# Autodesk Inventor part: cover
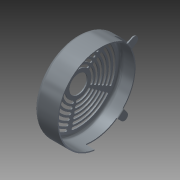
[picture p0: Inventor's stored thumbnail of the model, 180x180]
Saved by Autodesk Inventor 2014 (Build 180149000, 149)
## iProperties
Created: 2002-07
Part Number: cover
Document SubType Name: Modeling
Designer: ales
Density: 1 g/cm^3
Material: Generic
Appearance: Zinc
Control State: 0
Master: False
Checked Out: False
Shininess: 64.0
Length Units: 11269
Angle Units: 11279
Time Units: 11290
Mass Units: 11283
Length Display Precision: 3
Angle Display Precision: 2
Density: 0.0
Volumn: 0.0
Area: 0.0
PropertySet Name: Model Information
Author: PaulN
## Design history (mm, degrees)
sketch "Sketch1"
  geometry: L1 (-8.825, 0)-(-8.825, 107); L2 (3.175, 119)-(31.175, 119); L3 (-5.825, 0)-(-5.825, 107); L4 (3.175, 116)-(31.175, 116); L5 (-8.825, 0)-(-5.825, 0); L6 (31.175, 116)-(31.175, 119); L7 (-19.807, 0)-(39.672, 0) reference; A1 r 12 centre (3.175, 107) between (3.175, 119) and (-8.825, 107); A2 r 9 centre (3.175, 107) between (3.175, 116) and (-5.825, 107)
  constraints: 12 end point, 4 point on circle, 3 perpendicular, 2 centre point, 2 tangent, 1 collinear, 1 parallel, 1 vertical, 2 other
  dimensions: "d0" = 12 radius of A1; "d1" = 3 distance between parallel lines of L2 L4; "d3" = 40 distance between parallel lines of L1 L6; "d21" = 232 diameter of L4 L7
revolve "Revolution1" sketch "Sketch1" stored, may be unused: angle "d4" = 90 deg
sketch "Sketch2"
  geometry: L1 (-166.6, 0)-(166.6, 0) reference; L2 (32.997, 62.87)-(36.25, 69.068); L3 (38.092, 73.743)-(41.305, 79.962); L4 (43.183, 84.618)-(46.365, 90.853); L5 (62.412, 3.5)-(74.421, 3.5); L6 (74.421, 3.5)-(86.429, 3.5); L7 (86.429, 3.5)-(98.438, 3.5); L8 (0, 0)-(8.438, 18.096); L9 (27.894, 52.001)-(31.203, 58.169); L10 (22.778, 41.14)-(26.169, 47.264); L11 (50.403, 3.5)-(62.412, 3.5); L12 (17.637, 30.293)-(21.159, 36.343); L13 (38.395, 3.5)-(50.403, 3.5); C1 r 107 at (0, 0) reference; A1 r 102 centre (0, 0) between (101.936, 3.624) and (46.365, 90.853); A2 r 95 centre (0, 0) between (94.94, 3.376) and (43.183, 84.618); A3 r 3.5 centre (44.774, 87.736) between (46.365, 90.853) and (43.183, 84.618); A4 r 3.5 centre (98.438, 3.5) between (94.94, 3.376) and (101.936, 3.624); A5 r 90 centre (0, 0) between (89.926, 3.642) and (41.305, 79.962); A6 r 83 centre (0, 0) between (82.932, 3.358) and (38.092, 73.743); A7 r 3.5 centre (39.699, 76.852) between (41.305, 79.962) and (38.092, 73.743); A8 r 3.5 centre (86.429, 3.5) between (82.932, 3.358) and (89.926, 3.642); A9 r 78.003 centre (0, 0) between (77.917, 3.664) and (36.25, 69.068); A10 r 71.003 centre (0, 0) between (70.924, 3.336) and (32.997, 62.87); A11 r 3.5 centre (34.624, 65.969) between (36.25, 69.068) and (32.997, 62.87); A12 r 3.5 centre (74.421, 3.5) between (70.924, 3.336) and (77.917, 3.664); A13 r 66.01 centre (0, 0) between (65.906, 3.696) and (31.203, 58.169); A14 r 59.01 centre (0, 0) between (58.917, 3.304) and (27.894, 52.001); A15 r 3.5 centre (29.548, 55.085) between (31.203, 58.169) and (27.894, 52.001); A16 r 3.5 centre (62.412, 3.5) between (58.917, 3.304) and (65.906, 3.696); A17 r 54.025 centre (0, 0) between (53.895, 3.742) and (26.169, 47.264); A18 r 47.025 centre (0, 0) between (46.912, 3.258) and (22.778, 41.14); A19 r 3.5 centre (24.473, 44.202) between (26.169, 47.264) and (22.778, 41.14); A20 r 3.5 centre (50.403, 3.5) between (46.912, 3.258) and (53.895, 3.742); A21 r 42.054 centre (0, 0) between (41.88, 3.818) and (21.159, 36.343); A22 r 35.054 centre (0, 0) between (34.909, 3.182) and (17.637, 30.293); A23 r 3.5 centre (19.398, 33.318) between (21.159, 36.343) and (17.637, 30.293); A24 r 3.5 centre (38.395, 3.5) between (34.909, 3.182) and (41.88, 3.818)
  constraints: 49 point on circle, 33 tangent, 24 centre point, 24 end point, 12 coincident, 9 equal length, 3 collinear
  dimensions: "d6" = 5 radial gap between concentric circles of A1 C1; "d7" = 7 radial gap between concentric circles of A1 A2; "d16" = 5 radial gap between concentric circles of A5 A2 (= d6); "d17" = 65 deg angle of L1 L8
extrude "Extrusion1" cut sketch "Sketch2" stored distance "d10" = 25.4; taper "d11" = 0 deg
pattern_circular "Circular Pattern1" dims angle "d14" = 360 deg
sketch "Sketch3"
  geometry: C1 r 25 at (0, 0); 1 further point
  constraints: 1 centre point, 1 coincident
  dimensions: "d18" = 50 diameter of C1
extrude "Extrusion2" cut sketch "Sketch3" stored distance "d19" = 25.4; taper "d20" = 0 deg
sketch "Sketch4"
  geometry: L1 (58, 100.459)-(59.5, 103.057); L2 (0, 0)-(0, 19.788); L3 (-18.174, -114.567)-(-18.436, -117.563); A1 r 116 centre (0, 0) between (58, 100.459) and (-18.174, -114.567) reference; A2 r 119 centre (0, 0) between (59.5, 103.057) and (-18.436, -117.563) reference
  constraints: 6 end point, 4 point on circle, 1 point on line, 1 vertical
  dimensions: "d22" = 30 deg angle of L1 L2; "d23" = 5 deg angle of L3 L2
extrude "Extrusion3" join sketch "Sketch4" distance "d24" = 25; taper "d25" = 0 deg
fillet "Fillet1" dims "d26" = 3
sketch "Sketch5"
  geometry: L1 (77.134, 107.423)-(67.627, 97.916); L2 (92.397, 94.616)-(84.685, 83.603); L3 (0, 0)-(147.005, 0); L4 (0, 0)-(84.205, 100.352); L5 (84.685, 83.603)-(82.748, 81.294); L6 (67.627, 97.916)-(65.69, 95.608); A1 r 119 centre (0, 0) between (24.72, -116.404) and (24.72, 116.404) reference; A2 r 116 centre (0, 0) between (23.97, -113.496) and (24.171, 113.454) reference; A3 r 10 centre (84.205, 100.352) between (92.397, 94.616) and (77.134, 107.423); 1 further point
  constraints: 12 end point, 9 point on circle, 3 point on line, 2 parallel, 2 tangent, 1 centre point, 1 horizontal
  dimensions: "d27" = 20 diameter of A3; "d28" = 50 deg angle of L3 L4; "d29" = 12 distance of L4.end point (76.492, 91.159); "d31" = 5 deg angle of L1 L4; "d32" = 5 deg angle of L4 L2
extrude "Extrusion4" join sketch "Sketch5" distance "d33" = 3; taper "d34" = 0 deg
fillet "Fillet2" dims "d35" = 3
pattern_circular "Circular Pattern2" dims angle "d38" = 80 deg
body "Solid1"
